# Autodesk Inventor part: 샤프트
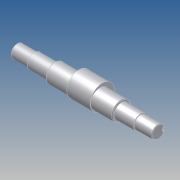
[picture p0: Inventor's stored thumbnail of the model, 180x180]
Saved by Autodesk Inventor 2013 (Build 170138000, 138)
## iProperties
Created: 2013-06
Part Number: 샤프트
Document SubType Name: Modeling
Designer: SeoGD™[esajin.kr]
Density: 1 g/cm^3
Material: 일반
Mass: 168.947 g
Surface Area: 248.524 cm^2
Volume: 168.947 cm^3
Author: SeoGD™[esajin.kr]
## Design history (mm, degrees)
sketch "스케치1"
  geometry: L1 (-20.5, -41.331)-(-20.5, 32.669) reference; L2 (7.5, -30.031)-(7.5, 21.369) reference; L3 (135.5, -30.331)-(135.5, 21.669) reference; L4 (121.5, 21.369)-(121.5, -30.031) reference; L5 (184.5, -4.331)-(-57.5, -4.331); L6 (184.5, -4.331)-(184.5, 6.669); L7 (154.5, 8.169)-(121.5, 8.169); L8 (121.5, 8.169)-(121.5, 11.669); L9 (121.5, 11.669)-(7.5, 11.669); L10 (7.5, 11.669)-(7.5, 8.169); L11 (7.5, 8.169)-(-27.5, 8.169); L12 (-27.5, 8.169)-(-27.5, 6.669); L13 (-27.5, 6.669)-(-57.5, 6.669); L14 (-57.5, 6.669)-(-57.5, -4.331); L15 (154.5, 8.169)-(154.5, 6.669); L16 (154.5, 6.669)-(184.5, 6.669); C1 r 32.5 at (64.5, -4.331) reference; 1 further point
  constraints: 24 end point, 8 perpendicular, 5 point on line, 3 parallel, 2 collinear
  dimensions: "d1" = 25 diameter of L11 L5; "d2" = 32 diameter of L9 L5; "d3" = 22 diameter of L13 L5; "d4" = 35 distance of L10.end L11.end; "d5" = 30 distance of L12.end L13.end; "d15" = 33 distance of L7.start L7.end; "d26" = 30 distance of L15.end L6.end
revolve "회전1" sketch "스케치1" stored, may be unused: angle "d6" = 90 deg
node "작업 평면1"
sketch "스케치2"
  geometry: C1 r 16 at (0, 0) reference; C2 r 16 at (0, 0) reference; C3 r 20.75 at (0, 4); C4 r 16 at (0, 0) reference; 1 further point
  constraints: 1 centre point, 1 vertical alignment
  dimensions: "d8" = 41.5 diameter of C3; "d25" = 4 distance of C3.centre C1.centre
extrude "돌출1" join sketch "스케치2" stored distance "d9" = 40; taper "d10" = 0 deg
chamfer "모따기1" distance "d11" = 1; stored, may be unused: second distance "d12" = 2, angle "d13" = 45 deg
node "작업 평면2"
sketch "스케치3"
  geometry: L1 (-15, -10)-(-15, 10) reference; L2 (-15, 3)-(0, 3); L3 (0, -3)-(-15, -3); A1 r 3 centre (0, 0) between (0, -3) and (0, 3); 2 further points
  constraints: 4 end point, 2 perpendicular, 2 point on circle, 2 point on line, 2 tangent, 1 centre point, 1 horizontal alignment, 1 midpoint
  dimensions: "d16" = 18 dimension on A1 L1; "d17" = 6 distance between parallel lines of L3 L2
extrude "돌출2" cut sketch "스케치3" distance "d18" = 3.5; taper "d19" = 0 deg
node "작업 평면3"
node "솔리드1"
mirror "대칭1"
node "참조1"
node "참조2"
node "참조3"
node "참조4"
node "참조5"
node "투영된 루프1"
